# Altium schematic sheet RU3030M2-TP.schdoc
size 127 x 101 mm
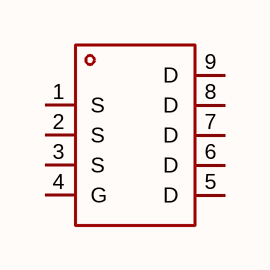
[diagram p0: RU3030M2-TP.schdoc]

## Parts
Q?  ru3030m2-tp  [PDFN3333-8_L3.1-W3.2-P0.65-LS3.4-BL]  (value not drawn)

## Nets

Not connected (* = marked no-connect by the designer): Q? 1(S) 2(S) 3(S) 4(G) 5(D) 6(D) 7(D) 8(D) 9(D)

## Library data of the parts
Q? = ru3030m2-tp: 漏源电压(Vdss):30V;连续漏极电流(Id):42A;导通电阻(RDS(on)):13mΩ@4.5V;耗散功率(Pd):35W;阈值电压(Vgs(th)):2.5V@250uA;; Manufacturer: TECH PUBLIC(台舟); AddInBom: yes; ModelId: 516601acd9f9456f95db3aec763cd5e7; ModelName: PDFN3333-8_L3.1-W3.2-H0.8-P0.65; ModelTransform: 129.921,131.8895,0,0,0,0,0,2.5,0; Drain to Source Voltage: 30V; Current - Continuous Drain(Id): 42A; Pd - Power Dissipation: 35W; Gate Charge(Qg): 7.1nC@4.5V; Input Capacitance(Ciss): 763pF@25V; Reverse Transfer Capacitance (Crss@Vds): 81pF@25V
